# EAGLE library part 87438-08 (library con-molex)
Wire-to-Board 1.50mm (.059") Pitch Header - Right Angle, SMT, Shrouded Source: http://www.molex.com/product/micro/87438.html
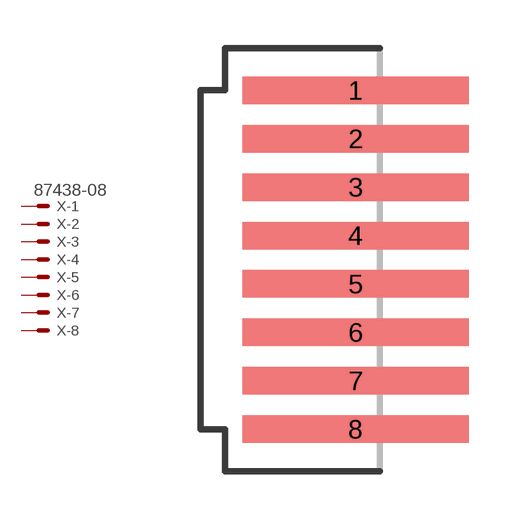
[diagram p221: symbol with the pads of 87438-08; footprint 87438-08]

Designator prefix X; gates -1=MV -2=M -3=M -4=M -5=M -6=M -7=M -8=M

## 87438-08 (OC_FARNELL: 1756939; OC_NEWARK: unknown)  [87438-08]
1  -1:S  pas
2  -2:S  pas
3  -3:S  pas
4  -4:S  pas
5  -5:S  pas
6  -6:S  pas
7  -7:S  pas
8  -8:S  pas

## Footprint 87438-08 (pad centres in mm)
Wire-to-Board 1.50mm (.059") Pitch Header - Right Angle, SMT, Shrouded Source: http://www.molex.com/product/micro/87438.html
smd 7 x 0.85: 1 0,5.25; 2 0,3.75; 3 0,2.25; 4 0,0.75; 5 0,-0.75; 6 0,-2.25; 7 0,-3.75; 8 0,-5.25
